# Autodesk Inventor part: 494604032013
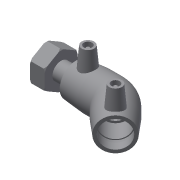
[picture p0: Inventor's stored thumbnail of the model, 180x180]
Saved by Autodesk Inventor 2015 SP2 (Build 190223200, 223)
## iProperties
Created: 2017-06
Part Number: 494604032013
Material: Generic
Description: PLASSON 45° ELBOW FEMALE FREE NUT TRANSITION 32-1.1/4"
Document SubType Name: Modeling
Designer: KIM
Mass: 55.0731 g
Surface Area: 148.067 cm^2
Volume: 55.0731 cm^3
Density: 1 g/cm^3
Appearance: Default
Author: KIM
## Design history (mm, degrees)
derived "494604.ipt"
feature "Solid1::494604.ipt"
tag "TaggingFeature1"
body "Solid1"
other parameters: "d2" = 44, "d4" = 23.75, "d5" = 39.6, "d8" = 168 deg, "d10" = 15.6, "d11" = 5.2, "d29" = 47, "d30" = 15, "d31" = 33.25, "d34" = 5 deg, "d41" = 4, "d42" = 14, "d43" = 0, "d49" = 32, "d50" = 27.2, "d51" = 15.6, "d52" = 39.39, "d54" = 135 deg, "d86" = 19.8, "d87" = 135 deg, "d88" = 95, "d90" = 39, "d91" = 0, "d92" = 39, "d93" = 0, "d101" = 3, "d102" = 0, "d108" = 23, "d110" = 34, "d112" = 58.428, "d113" = 38.952, "d139" = 27.2664, "d140" = 23, "d141" = 17, "d142" = 1.7, "d143" = 3.4, "d144" = 13.6, "d145" = 31.1616, "d146" = 1.9476, "d150" = 0, "d151" = 1.6, "d_" = 32, "L_" = 129, "L_1" = 39, "D_" = 23, "A_" = 47, "d_2" = 12, "L_2" = 34, "G_" = 38.952, "D_1" = 44
